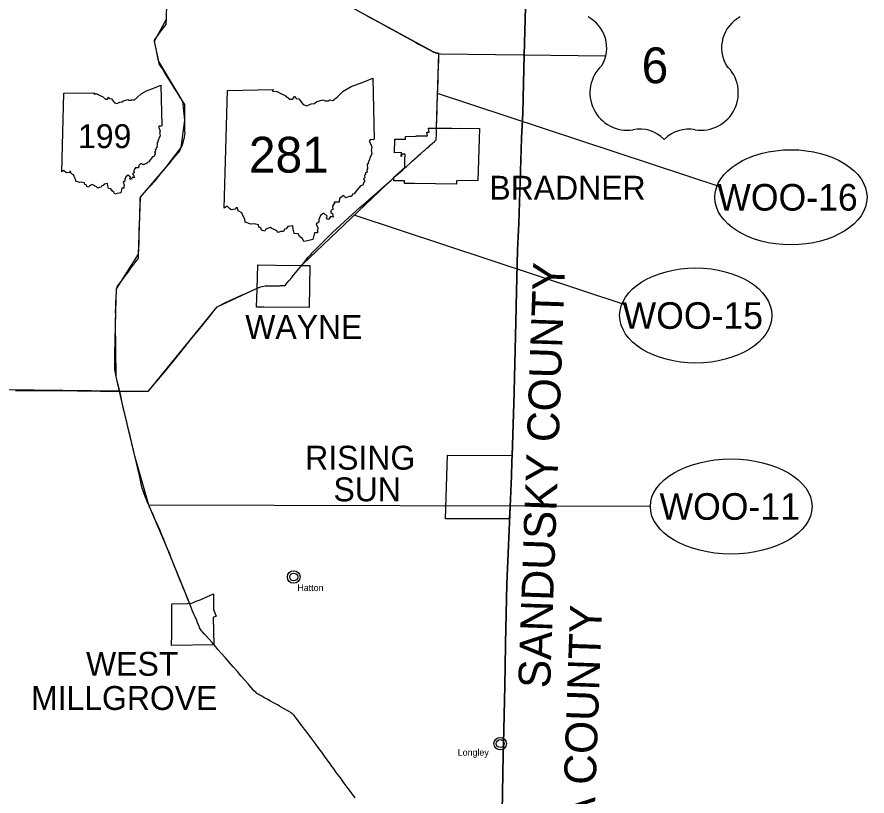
# Model space of a CAD drawing. Extents: x 0 to 851, y 0 to 440.
# Drawn here: x 367.7 to 457.1, y 111.8 to 193.8 of the extents above; entities that cross this region are included whole.
import ezdxf

# ---------------------------------------------------------------- set-up
doc = ezdxf.new("R2010")
doc.units = 0
for name, color, linetype in [('DV_X_Corp_Line', 7, 'Continuous'), ('GM_X_Adjacent_County_Text', 7, 'Continuous'), ('GM_X_Corporation_Text', 7, 'Continuous'), ('GM_X_County', 7, 'Continuous'), ('GM_X_State_Route', 7, 'Continuous'), ('GM_X_US_Route', 7, 'Continuous'), ('PV_P_Text', 7, 'Continuous'), ('RD_P_Fence', 7, 'Continuous'), ('SH_Data', 7, 'Continuous')]:
    doc.layers.add(name, color=color, linetype=linetype)

msp = doc.modelspace()

# ---------------------------------------------------------------- linework, layer by layer
at = {"layer": 'DV_X_Corp_Line'}
for points in [[(407.339, 176.523), (407.35, 176.9), (408.516, 177.93), (408.528, 178.728), (408.539, 179.319), (408.162, 179.317), (408.154, 179.073), (408.131, 179.073), (408.146, 179.485), (407.425, 179.481), (407.453, 180.917), (408.58, 180.914), (408.588, 181.189), (409.697, 181.207), (409.699, 181.248), (410.894, 181.262), (410.843, 181.626), (411.064, 181.654), (411.013, 182.06), (411.919, 182.061), (411.918, 182.042), (413.461, 182.054), (413.46, 182.037), (414.354, 182.044), (416.372, 182.037), (416.335, 180.956), (416.269, 178.705), (416.196, 176.538), (413.96, 176.51), (413.945, 176.181), (411.747, 176.213), (409.534, 176.242), (408.476, 176.238), (408.477, 176.529), (407.764, 176.525)], [(392.925, 163.245), (392.98, 165.128), (393.064, 167.68), (394.917, 167.663), (397.64, 167.618), (398.539, 167.615), (398.486, 165.412), (398.44, 163.208), (393.671, 163.228)], [(412.786, 140.984), (413.01, 147.668), (419.777, 147.616), (419.727, 145.668), (419.477, 140.985)], [(384.024, 132.03), (385.659, 132.056), (385.865, 132.144), (385.911, 132.029), (386.298, 132.186), (386.571, 132.293), (386.991, 132.465), (388.388, 133.063), (388.391, 131.443), (388.684, 130.724), (388.363, 130.592), (388.427, 127.73), (383.991, 127.647), (384.023, 128.853), (384.019, 128.924)]]:
    msp.add_lwpolyline(points, close=True, dxfattribs=at)
for centre, radius in [((396.832, 134.852), 0.658), ((396.832, 134.852), 0.417), ((418.543, 117.325), 0.658), ((418.543, 117.325), 0.417)]:
    msp.add_circle(centre, radius, dxfattribs=at)
at = {"layer": 'GM_X_County'}
msp.add_lwpolyline([(421.3, 198.608), (421.066, 189.761), (420.947, 185.241), (420.905, 183.652), (420.786, 180.989), (420.516, 172.023), (420.373, 169.238), (420.235, 163.418), (420.228, 163.133), (420.02, 154.369), (420.017, 154.224), (419.791, 147.557), (419.776, 147.113), (419.757, 146.556), (419.735, 145.907), (419.721, 145.492), (419.718, 145.41), (419.694, 144.718), (419.665, 143.862), (419.331, 136.55), (419.224, 134.123), (419.115, 127.854), (419.109, 127.668), (419.027, 123.397), (418.929, 118.8), (418.835, 114.486), (418.831, 114.371), (418.777, 111.943), (418.648, 105.559)], dxfattribs=at)
at = {"layer": 'GM_X_State_Route'}
for points in [[(385.007, 180.01), (385.089, 180.188), (385.11, 180.248), (385.214, 180.538), (385.281, 180.856), (385.337, 181.086), (385.387, 181.37), (385.407, 181.538), (385.391, 181.703), (385.389, 181.934), (385.392, 182.367), (385.39, 182.891), (385.391, 183.391), (385.394, 183.979), (385.385, 184.493), (385.363, 184.564), (385.181, 184.857), (384.938, 185.238), (384.597, 185.776), (384.334, 186.191), (384.003, 186.726), (383.704, 187.206), (383.315, 187.825), (382.981, 188.353), (382.845, 188.559), (382.736, 188.737), (382.694, 188.825), (382.663, 188.91), (382.636, 189.058), (382.552, 189.43), (382.467, 189.84), (382.355, 190.389), (382.252, 190.845), (382.192, 191.123), (382.184, 191.21), (382.2, 191.31), (382.239, 191.377), (382.333, 191.522), (382.529, 191.793), (382.794, 192.159), (383.013, 192.449), (383.248, 192.756), (383.408, 192.964), (383.433, 193.038), (383.44, 193.511), (383.439, 193.729), (383.439, 193.781)], [(411.848, 181.974), (411.848, 181.977), (411.852, 182.189), (411.877, 183.018), (411.899, 183.84), (411.926, 184.602), (411.955, 185.454), (411.976, 186.266), (412.002, 187.024), (412.032, 187.739), (412.049, 188.514), (412.075, 189.238), (412.096, 189.896)], [(409.574, 178.835), (409.579, 178.839), (409.822, 179.051), (409.92, 179.138), (410.192, 179.379), (410.522, 179.672), (410.579, 179.723), (410.678, 179.81), (410.863, 179.975), (411.019, 180.112), (411.154, 180.23), (411.229, 180.296), (411.38, 180.43), (411.62, 180.643), (411.806, 180.83), (411.836, 181.454), (411.848, 181.974)], [(381.457, 175.665), (381.553, 175.767), (381.642, 175.862), (381.933, 176.17), (382.112, 176.364), (382.251, 176.515), (382.39, 176.703), (382.603, 176.979), (382.855, 177.28), (383.144, 177.622), (383.427, 177.972), (383.755, 178.354), (384.093, 178.756), (384.411, 179.156), (384.742, 179.548), (384.839, 179.683), (384.951, 179.886), (385.007, 180.01)], [(408.457, 177.839), (408.458, 177.839), (408.688, 178.042), (409.061, 178.386), (409.335, 178.625), (409.574, 178.835)], [(407.336, 176.846), (407.478, 176.974), (407.89, 177.338), (408.287, 177.688), (408.457, 177.839)], [(403.826, 173.739), (403.964, 173.859), (404.364, 174.219), (404.724, 174.537), (405.163, 174.92), (405.553, 175.267), (406.029, 175.69), (406.512, 176.112), (407.03, 176.571), (407.335, 176.846), (407.336, 176.846)], [(380.672, 173.799), (380.674, 173.862), (380.687, 174.184), (380.697, 174.68), (380.716, 174.784), (380.756, 174.894), (380.822, 174.986), (380.985, 175.163), (381.331, 175.531), (381.457, 175.665)], [(380.613, 172.01), (380.634, 172.778), (380.659, 173.486), (380.672, 173.799)], [(400.909, 171.093), (403.826, 173.739)], [(380.052, 167.781), (380.255, 168.052), (380.468, 168.332), (380.497, 168.412), (380.513, 168.502), (380.52, 168.801), (380.542, 169.371), (380.563, 170.052), (380.58, 170.694), (380.591, 171.382), (380.613, 172.01)], [(398.668, 168.823), (398.78, 168.937), (399.168, 169.332), (399.504, 169.667), (399.851, 170.018), (400.185, 170.353), (400.49, 170.665), (400.868, 171.053), (400.909, 171.093)], [(397.729, 167.7), (397.738, 167.711), (398.015, 168.075), (398.215, 168.332), (398.353, 168.5), (398.522, 168.674), (398.666, 168.821), (398.668, 168.823)], [(378.116, 163.206), (378.127, 163.642), (378.154, 164.303), (378.182, 164.85), (378.2, 165.175), (378.219, 165.262), (378.255, 165.345), (378.305, 165.445), (378.399, 165.567), (378.632, 165.883), (378.886, 166.219), (379.141, 166.562), (379.409, 166.925), (379.709, 167.323), (379.994, 167.704), (380.015, 167.732), (380.052, 167.781)], [(396.023, 165.643), (396.154, 165.802), (396.331, 166.017), (396.358, 166.05), (396.62, 166.363), (396.774, 166.549), (396.841, 166.63), (397.188, 167.045), (397.334, 167.227), (397.576, 167.514), (397.727, 167.698), (397.729, 167.7)], [(393.004, 165.227), (393.03, 165.239), (393.16, 165.301), (393.195, 165.315), (393.266, 165.346), (393.347, 165.371), (393.509, 165.414), (393.684, 165.445), (393.836, 165.461), (394.094, 165.462), (394.44, 165.467), (394.796, 165.463), (395.109, 165.463), (395.28, 165.469), (395.344, 165.481), (395.412, 165.503), (395.476, 165.515), (395.594, 165.519), (395.919, 165.515), (396.023, 165.642), (396.023, 165.643)], [(385.521, 159.229), (385.813, 159.59), (386.266, 160.148), (386.67, 160.652), (387.122, 161.207), (387.553, 161.741), (387.892, 162.16), (388.233, 162.575), (388.61, 163.044), (388.778, 163.261), (388.834, 163.314), (388.973, 163.389), (389.449, 163.62), (390.097, 163.918), (390.823, 164.241), (391.352, 164.481), (391.878, 164.718), (392.387, 164.949), (392.835, 165.147), (393.004, 165.227)], [(378.533, 154.38), (378.427, 154.829), (378.294, 155.387), (378.173, 155.941), (378.073, 156.337), (378.037, 156.512), (378.027, 156.64), (378.018, 156.835), (378.022, 157.232), (378.033, 157.917), (378.035, 158.676), (378.043, 159.371), (378.054, 160.157), (378.076, 160.902), (378.091, 161.6), (378.106, 162.309), (378.105, 162.806), (378.116, 163.206)], [(382.814, 155.902), (383.007, 156.123), (383.414, 156.617), (383.78, 157.073), (384.17, 157.558), (384.56, 158.043), (384.871, 158.429), (385.13, 158.749), (385.437, 159.125), (385.521, 159.229)], [(379.311, 154.387), (379.445, 154.387), (380.057, 154.391), (380.588, 154.394), (381.112, 154.391), (381.558, 154.389), (381.803, 154.696), (382.15, 155.124), (382.594, 155.648), (382.814, 155.902)], [(367.557, 154.472), (367.732, 154.471), (367.941, 154.473), (368.485, 154.469), (369.111, 154.466), (369.753, 154.467), (370.294, 154.459), (370.855, 154.458), (371.464, 154.463), (372.029, 154.459), (372.577, 154.461), (373.038, 154.456), (373.515, 154.451), (374.056, 154.44), (374.6, 154.43), (375.165, 154.422), (375.502, 154.419), (375.753, 154.417), (376.513, 154.404), (377.084, 154.397), (377.642, 154.391)], [(377.642, 154.391), (377.915, 154.389), (378.533, 154.38)], [(378.533, 154.38), (378.917, 154.387), (379.311, 154.387)], [(385.847, 132.128), (385.822, 132.188), (385.662, 132.575), (385.44, 133.146), (385.204, 133.715), (385.054, 134.081), (384.895, 134.477), (384.715, 134.894), (384.492, 135.453), (384.301, 135.944), (384.107, 136.435), (384.021, 136.643), (383.941, 136.835), (383.751, 137.343), (383.556, 137.804), (383.381, 138.251), (383.167, 138.779), (383.008, 139.186), (382.747, 139.816), (382.438, 140.497), (382.266, 140.869), (382.069, 141.308), (381.898, 141.702), (381.745, 142.052), (381.593, 142.391), (381.456, 142.694), (381.343, 142.989), (381.21, 143.335), (381.097, 143.614), (381.003, 143.912), (380.907, 144.206), (380.79, 144.65), (380.703, 145.041), (380.605, 145.535), (380.461, 146.099), (380.289, 146.846), (380.119, 147.573), (379.934, 148.354), (379.765, 149.08), (379.579, 149.838), (379.425, 150.487), (379.27, 151.152), (379.104, 151.862), (379.069, 152.007), (378.979, 152.379), (378.801, 153.153), (378.635, 153.897), (378.533, 154.38)], [(385.881, 132.046), (385.856, 132.108), (385.847, 132.128)], [(386.383, 130.818), (386.347, 130.887), (386.197, 131.262), (385.936, 131.915), (385.881, 132.046)], [(387.485, 128.815), (387.458, 128.846), (387.25, 129.082), (387.145, 129.203), (387.025, 129.349), (386.981, 129.403), (386.928, 129.518), (386.87, 129.67), (386.757, 129.941), (386.624, 130.272), (386.464, 130.661), (386.383, 130.818)], [(388.362, 127.81), (388.24, 127.949), (387.884, 128.367), (387.585, 128.705), (387.485, 128.815)], [(403.294, 111.621), (402.908, 112.147), (402.555, 112.62), (402.141, 113.177), (401.769, 113.688), (401.446, 114.115), (401.227, 114.407), (401.117, 114.569), (400.837, 114.957), (400.476, 115.454), (400.144, 115.903), (399.778, 116.412), (399.416, 116.902), (399.139, 117.278), (398.717, 117.844), (398.338, 118.362), (397.979, 118.836), (397.658, 119.261), (397.299, 119.733), (397.028, 120.109), (396.842, 120.336), (396.727, 120.44), (396.63, 120.509), (396.538, 120.577), (396.405, 120.657), (396.193, 120.773), (395.824, 120.974), (395.453, 121.196), (395.112, 121.39), (394.773, 121.573), (394.387, 121.795), (394.034, 122.001), (393.695, 122.187), (393.459, 122.319), (393.258, 122.432), (393.094, 122.519), (392.965, 122.609), (392.83, 122.726), (392.647, 122.881), (392.561, 122.998), (392.369, 123.229), (392.043, 123.603), (391.668, 124.025), (391.318, 124.429), (390.902, 124.909), (390.468, 125.415), (390.016, 125.919), (389.605, 126.383), (389.21, 126.834), (388.855, 127.242), (388.631, 127.489), (388.421, 127.743), (388.362, 127.81)]]:
    msp.add_lwpolyline(points, dxfattribs=at)
at = {"layer": 'GM_X_US_Route'}
for points in [[(421.066, 189.761), (421.066, 189.761), (421.3, 198.608), (421.534, 207.502), (421.647, 211.926), (421.65, 212.075)], [(404.525, 193.884), (405.126, 193.558), (405.763, 193.209), (406.344, 192.884), (406.845, 192.611), (407.257, 192.387), (407.735, 192.128), (408.203, 191.872), (408.644, 191.628), (409.109, 191.376), (409.55, 191.141), (409.962, 190.91), (410.436, 190.655), (410.964, 190.371), (411.386, 190.14), (411.575, 190.049), (411.732, 189.991), (411.885, 189.951), (412.096, 189.896)], [(412.096, 189.896), (412.263, 189.876), (429.637, 189.649)], [(420.749, 179.758), (420.786, 180.989), (420.905, 183.652), (420.947, 185.241), (421.066, 189.761)], [(419.793, 147.614), (420.017, 154.224), (420.02, 154.369), (420.228, 163.133), (420.235, 163.418), (420.373, 169.238), (420.516, 172.023), (420.749, 179.758)], [(419.623, 142.953), (419.665, 143.862), (419.694, 144.718), (419.718, 145.41), (419.721, 145.492), (419.735, 145.907), (419.757, 146.556), (419.776, 147.113), (419.791, 147.557), (419.793, 147.614)], [(419.331, 136.55), (419.623, 142.953)], [(419.109, 127.668), (419.115, 127.854), (419.224, 134.123), (419.331, 136.55)], [(418.582, 101.337), (418.647, 105.498), (418.648, 105.559), (418.777, 111.943), (418.831, 114.371), (418.835, 114.486), (418.929, 118.8), (419.027, 123.397), (419.109, 127.668)]]:
    msp.add_lwpolyline(points, dxfattribs=at)
at = {"layer": 'PV_P_Text'}
for p, q in [((389.527, 173.659), (389.873, 186.031)), ((389.527, 173.659), (389.873, 186.031)), ((372.437, 177.48), (372.668, 185.728)), ((372.437, 177.48), (372.668, 185.728))]:
    msp.add_line(p, q, dxfattribs=at)
for points in [[(389.873, 186.031), (394.673, 186.112), (394.598, 185.962), (395.052, 185.931), (395.533, 185.667), (395.939, 185.5), (396.437, 185.106), (396.735, 185.111), (396.861, 185.433), (397.089, 185.184), (397.36, 185.14), (397.828, 184.548), (398.214, 184.419), (398.677, 184.622), (399.023, 184.656), (399.275, 184.856), (399.934, 185.028), (400.118, 184.925), (400.467, 184.946), (400.642, 185.022), (400.946, 184.954), (401.482, 185.404), (402.033, 185.934), (402.881, 186.435), (404.147, 186.909), (405.148, 187.333), (405.293, 180.912)], [(389.873, 186.031), (394.673, 186.112), (394.598, 185.962), (395.052, 185.931), (395.533, 185.667), (395.939, 185.5), (396.437, 185.106), (396.735, 185.111), (396.861, 185.433), (397.089, 185.184), (397.36, 185.14), (397.828, 184.548), (398.214, 184.419), (398.677, 184.622), (399.023, 184.656), (399.275, 184.856), (399.934, 185.028), (400.118, 184.925), (400.467, 184.946), (400.642, 185.022), (400.946, 184.954), (401.482, 185.404), (402.033, 185.934), (402.881, 186.435), (404.147, 186.909), (405.148, 187.333), (405.293, 180.912)], [(372.668, 185.728), (375.868, 185.782), (375.818, 185.682), (376.12, 185.662), (376.441, 185.485), (376.712, 185.374), (377.044, 185.112), (377.242, 185.115), (377.326, 185.33), (377.478, 185.164), (377.659, 185.134), (377.971, 184.739), (378.228, 184.654), (378.537, 184.789), (378.767, 184.811), (378.936, 184.945), (379.375, 185.06), (379.497, 184.991), (379.73, 185.005), (379.847, 185.056), (380.05, 185.01), (380.407, 185.31), (380.774, 185.664), (381.339, 185.998), (382.184, 186.314), (382.851, 186.596), (382.948, 182.316)], [(372.668, 185.728), (375.868, 185.782), (375.818, 185.682), (376.12, 185.662), (376.441, 185.485), (376.712, 185.374), (377.044, 185.112), (377.242, 185.115), (377.326, 185.33), (377.478, 185.164), (377.659, 185.134), (377.971, 184.739), (378.228, 184.654), (378.537, 184.789), (378.767, 184.811), (378.936, 184.945), (379.375, 185.06), (379.497, 184.991), (379.73, 185.005), (379.847, 185.056), (380.05, 185.01), (380.407, 185.31), (380.774, 185.664), (381.339, 185.998), (382.184, 186.314), (382.851, 186.596), (382.948, 182.316)], [(382.948, 182.316), (382.849, 182.256), (382.696, 182.284), (382.593, 182.164), (382.72, 181.964), (382.781, 181.752), (382.727, 181.519), (382.78, 181.326), (382.744, 181.165), (382.648, 181.005), (382.614, 180.852), (382.532, 180.692), (382.539, 180.601), (382.461, 180.53), (382.475, 180.262), (382.436, 180.114), (382.449, 179.986), (382.323, 179.953), (382.352, 179.847), (382.271, 179.765), (382.288, 179.625), (382.197, 179.535), (382.286, 179.355), (382.214, 179.298), (382.155, 179.08), (381.993, 179.036), (381.667, 178.636), (381.552, 178.485), (381.423, 178.448), (381.352, 178.292), (381.193, 178.292), (380.953, 178.185), (380.798, 178.369), (380.525, 178.147), (380.494, 177.89), (380.15, 177.898), (380.163, 177.768), (380.086, 177.73), (380.016, 177.6), (380.057, 177.368), (379.896, 177.309), (379.915, 177.175), (380.018, 177.092), (380.064, 176.836), (379.893, 176.888), (379.753, 176.671), (379.608, 176.722), (379.656, 176.905), (379.412, 177.126), (379.181, 176.949), (379.061, 176.667), (379.059, 176.477), (378.888, 176.362), (378.998, 176.094), (378.978, 175.91), (378.981, 175.734), (378.766, 175.74), (378.636, 175.267)], [(382.948, 182.316), (382.849, 182.256), (382.696, 182.284), (382.593, 182.164), (382.72, 181.964), (382.781, 181.752), (382.727, 181.519), (382.78, 181.326), (382.744, 181.165), (382.648, 181.005), (382.614, 180.852), (382.532, 180.692), (382.539, 180.601), (382.461, 180.53), (382.475, 180.262), (382.436, 180.114), (382.449, 179.986), (382.323, 179.953), (382.352, 179.847), (382.271, 179.765), (382.288, 179.625), (382.197, 179.535), (382.286, 179.355), (382.214, 179.298), (382.155, 179.08), (381.993, 179.036), (381.667, 178.636), (381.552, 178.485), (381.423, 178.448), (381.352, 178.292), (381.193, 178.292), (380.953, 178.185), (380.798, 178.369), (380.525, 178.147), (380.494, 177.89), (380.15, 177.898), (380.163, 177.768), (380.086, 177.73), (380.016, 177.6), (380.057, 177.368), (379.896, 177.309), (379.915, 177.175), (380.018, 177.092), (380.064, 176.836), (379.893, 176.888), (379.753, 176.671), (379.608, 176.722), (379.656, 176.905), (379.412, 177.126), (379.181, 176.949), (379.061, 176.667), (379.059, 176.477), (378.888, 176.362), (378.998, 176.094), (378.978, 175.91), (378.981, 175.734), (378.766, 175.74), (378.636, 175.267)], [(405.293, 180.912), (405.145, 180.822), (404.915, 180.865), (404.761, 180.685), (404.952, 180.384), (405.042, 180.067), (404.962, 179.717), (405.041, 179.428), (404.988, 179.187), (404.843, 178.946), (404.793, 178.717), (404.67, 178.476), (404.68, 178.341), (404.563, 178.234), (404.584, 177.832), (404.525, 177.61), (404.545, 177.418), (404.355, 177.367), (404.399, 177.209), (404.278, 177.086), (404.304, 176.875), (404.167, 176.741), (404.3, 176.472), (404.193, 176.386), (404.104, 176.059), (403.861, 175.992), (403.372, 175.393), (403.2, 175.166), (403.007, 175.11), (402.9, 174.877), (402.662, 174.876), (402.301, 174.715), (402.068, 174.993), (401.659, 174.659), (401.612, 174.273), (401.096, 174.285), (401.116, 174.09), (401.001, 174.033), (400.896, 173.838), (400.957, 173.491), (400.715, 173.402), (400.744, 173.201), (400.899, 173.077), (400.968, 172.692), (400.711, 172.77), (400.501, 172.445), (400.284, 172.522), (400.355, 172.797), (399.989, 173.127), (399.643, 172.863), (399.463, 172.439), (399.461, 172.154), (399.203, 171.982), (399.368, 171.58), (399.338, 171.303), (399.343, 171.04), (399.021, 171.049), (398.826, 170.338)], [(405.293, 180.912), (405.145, 180.822), (404.915, 180.865), (404.761, 180.685), (404.952, 180.384), (405.042, 180.067), (404.962, 179.717), (405.041, 179.428), (404.988, 179.187), (404.843, 178.946), (404.793, 178.717), (404.67, 178.476), (404.68, 178.341), (404.563, 178.234), (404.584, 177.832), (404.525, 177.61), (404.545, 177.418), (404.355, 177.367), (404.399, 177.209), (404.278, 177.086), (404.304, 176.875), (404.167, 176.741), (404.3, 176.472), (404.193, 176.386), (404.104, 176.059), (403.861, 175.992), (403.372, 175.393), (403.2, 175.166), (403.007, 175.11), (402.9, 174.877), (402.662, 174.876), (402.301, 174.715), (402.068, 174.993), (401.659, 174.659), (401.612, 174.273), (401.096, 174.285), (401.116, 174.09), (401.001, 174.033), (400.896, 173.838), (400.957, 173.491), (400.715, 173.402), (400.744, 173.201), (400.899, 173.077), (400.968, 172.692), (400.711, 172.77), (400.501, 172.445), (400.284, 172.522), (400.355, 172.797), (399.989, 173.127), (399.643, 172.863), (399.463, 172.439), (399.461, 172.154), (399.203, 171.982), (399.368, 171.58), (399.338, 171.303), (399.343, 171.04), (399.021, 171.049), (398.826, 170.338)], [(378.636, 175.267), (378.263, 175.176), (378.003, 175.122), (377.912, 175.337), (377.727, 175.45), (377.606, 175.667), (377.34, 175.697), (377.277, 175.994), (377.247, 176.235), (376.883, 176.176), (376.783, 176.028), (376.654, 175.989), (376.579, 175.84), (376.403, 175.827), (376.214, 175.757), (376.091, 175.903), (375.781, 176.05), (375.642, 176.125), (375.351, 176.008), (375.289, 175.869), (375.058, 175.93), (375.003, 176.085), (374.863, 176.132), (374.832, 176.296), (374.533, 176.383), (374.304, 176.349), (373.9, 176.481), (373.875, 176.697), (373.738, 176.96), (373.666, 177.143), (373.411, 177.283), (373.359, 177.5), (373.277, 177.494), (373.202, 177.406), (372.919, 177.365), (372.805, 177.454), (372.647, 177.606), (372.437, 177.48)], [(378.636, 175.267), (378.263, 175.176), (378.003, 175.122), (377.912, 175.337), (377.727, 175.45), (377.606, 175.667), (377.34, 175.697), (377.277, 175.994), (377.247, 176.235), (376.883, 176.176), (376.783, 176.028), (376.654, 175.989), (376.579, 175.84), (376.403, 175.827), (376.214, 175.757), (376.091, 175.903), (375.781, 176.05), (375.642, 176.125), (375.351, 176.008), (375.289, 175.869), (375.058, 175.93), (375.003, 176.085), (374.863, 176.132), (374.832, 176.296), (374.533, 176.383), (374.304, 176.349), (373.9, 176.481), (373.875, 176.697), (373.738, 176.96), (373.666, 177.143), (373.411, 177.283), (373.359, 177.5), (373.277, 177.494), (373.202, 177.406), (372.919, 177.365), (372.805, 177.454), (372.647, 177.606), (372.437, 177.48)], [(398.826, 170.338), (398.266, 170.203), (397.877, 170.121), (397.74, 170.444), (397.461, 170.614), (397.28, 170.939), (396.881, 170.983), (396.787, 171.429), (396.742, 171.792), (396.196, 171.702), (396.046, 171.481), (395.853, 171.421), (395.74, 171.198), (395.476, 171.18), (395.193, 171.075), (395.007, 171.293), (394.543, 171.513), (394.335, 171.626), (393.898, 171.45), (393.805, 171.242), (393.458, 171.334), (393.377, 171.566), (393.167, 171.636), (393.12, 171.882), (392.671, 172.013), (392.328, 171.961), (391.721, 172.16), (391.685, 172.484), (391.478, 172.879), (391.37, 173.153), (390.987, 173.363), (390.91, 173.689), (390.787, 173.679), (390.675, 173.547), (390.25, 173.486), (390.08, 173.619), (389.842, 173.847), (389.527, 173.659)], [(398.826, 170.338), (398.266, 170.203), (397.877, 170.121), (397.74, 170.444), (397.461, 170.614), (397.28, 170.939), (396.881, 170.983), (396.787, 171.429), (396.742, 171.792), (396.196, 171.702), (396.046, 171.481), (395.853, 171.421), (395.74, 171.198), (395.476, 171.18), (395.193, 171.075), (395.007, 171.293), (394.543, 171.513), (394.335, 171.626), (393.898, 171.45), (393.805, 171.242), (393.458, 171.334), (393.377, 171.566), (393.167, 171.636), (393.12, 171.882), (392.671, 172.013), (392.328, 171.961), (391.721, 172.16), (391.685, 172.484), (391.478, 172.879), (391.37, 173.153), (390.987, 173.363), (390.91, 173.689), (390.787, 173.679), (390.675, 173.547), (390.25, 173.486), (390.08, 173.619), (389.842, 173.847), (389.527, 173.659)]]:
    msp.add_lwpolyline(points, dxfattribs=at)
for centre, radius, start, end in [((426.1, 190.517), 3.642, 329.11751, 62.61081), ((426.1, 190.517), 3.642, 329.11751, 62.61081), ((445.458, 190.517), 3.642, 117.38919, 210.88249), ((445.458, 190.517), 3.642, 117.38919, 210.88249), ((431.906, 185.774), 3.93, 133.00455, 278.72816), ((431.906, 185.774), 3.93, 133.00455, 278.72816), ((439.652, 185.774), 3.93, 261.27184, 46.99545), ((439.652, 185.774), 3.93, 261.27184, 46.99545), ((433.226, 178.45), 3.515, 43.41772, 101.87423), ((433.226, 178.45), 3.515, 43.41772, 101.87423), ((438.405, 178.217), 3.731, 79.96126, 134.74679), ((438.405, 178.217), 3.731, 79.96126, 134.74679)]:
    msp.add_arc(centre, radius, start, end, dxfattribs=at)
at = {"layer": 'RD_P_Fence'}
for p, q in [((411.852, 182.189), (412.096, 189.896)), ((397.727, 167.698), (407.335, 176.846))]:
    msp.add_line(p, q, dxfattribs=at)
for points in [[(412.096, 189.896), (411.575, 190.049), (396.032, 198.547), (395.866, 198.634), (395.526, 198.759), (395.366, 198.8), (395.044, 198.82), (389.771, 198.714), (384.381, 198.624), (383.676, 198.633), (382.876, 198.728), (382.496, 198.855), (381.875, 199.17), (379.376, 201.993), (378.946, 202.393), (378.255, 202.865), (376.986, 203.089)], [(385.822, 132.188), (383.381, 138.251), (381.593, 142.391), (380.119, 147.573), (378.801, 153.153), (378.173, 155.941), (378.091, 161.6), (378.2, 165.175), (380.52, 168.801), (380.716, 174.784), (383.427, 177.972), (385.007, 180.01), (385.39, 182.891), (385.181, 184.857), (382.636, 189.058), (382.184, 191.21), (383.44, 193.511), (383.517, 197.183), (383.942, 198.631)], [(378.533, 154.38), (381.558, 154.389), (388.778, 163.261), (392.835, 165.147), (392.987, 165.226)], [(378.533, 154.38), (366.547, 154.542), (361.361, 154.507), (356.621, 154.514), (348.118, 154.531), (324.919, 155.036), (320.168, 155.14), (313.351, 155.438)]]:
    msp.add_lwpolyline(points, dxfattribs=at)
at = {"layer": 'SH_Data'}
for p, q in [((441.787, 175.867), (411.964, 185.712)), ((431.776, 163.432), (403.196, 172.904)), ((434.33, 142.267), (381.593, 142.391))]:
    msp.add_line(p, q, dxfattribs=at)
for centre, major_axis, ratio in [((449.111, 174.788), (8, 0), 0.625), ((439.1, 162.353), (8, 0), 0.625), ((442.83, 142.267), (8.5, 0), 0.588235)]:
    msp.add_ellipse(centre, major_axis=major_axis, ratio=ratio, dxfattribs=at)

# ---------------------------------------------------------------- texts
at = {"layer": 'DV_X_Corp_Line'}
for s, p in [('Hatton', (397.21, 133.368)), ('Longley', (414.073, 116.056))]:
    msp.add_text(s, height=0.6979, rotation=0.00001, dxfattribs=at).set_placement(p)
at = {"layer": 'GM_X_Adjacent_County_Text'}
for s, p in [('SANDUSKY COUNTY', (423.784, 123.11)), ('SENECA COUNTY', (427.888, 93.292))]:
    msp.add_text(s, height=3.35, rotation=87.97475, dxfattribs=at).set_placement(p)
at = {"layer": 'GM_X_Corporation_Text'}
for s, p in [('BRADNER', (417.402, 174.533)), ('WAYNE', (391.731, 159.897)), ('RISING', (398.035, 146.141)), ('SUN', (401.009, 142.811)), ('WEST', (374.992, 124.463)), ('MILLGROVE', (369.202, 120.871))]:
    msp.add_text(s, height=2.5126, rotation=0.00001, dxfattribs=at).set_placement(p)
at = {"layer": 'PV_P_Text'}
for s, height, p in [('6', 3.769, (433.413, 186.783)), ('199', 2.5126, (374.15, 179.961)), ('281', 3.7688, (392.112, 177.38))]:
    msp.add_text(s, height=height, dxfattribs=at).set_placement(p)
at = {"layer": 'SH_Data'}
for s, p in [('WOO-16', (441.364, 173.388)), ('WOO-15', (431.407, 160.953)), ('WOO-11', (435.291, 140.867))]:
    msp.add_text(s, height=2.8, dxfattribs=at).set_placement(p)

doc.saveas('drawing.dxf')
